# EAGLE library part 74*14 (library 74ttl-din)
Hex schmitt trigger INVERTER
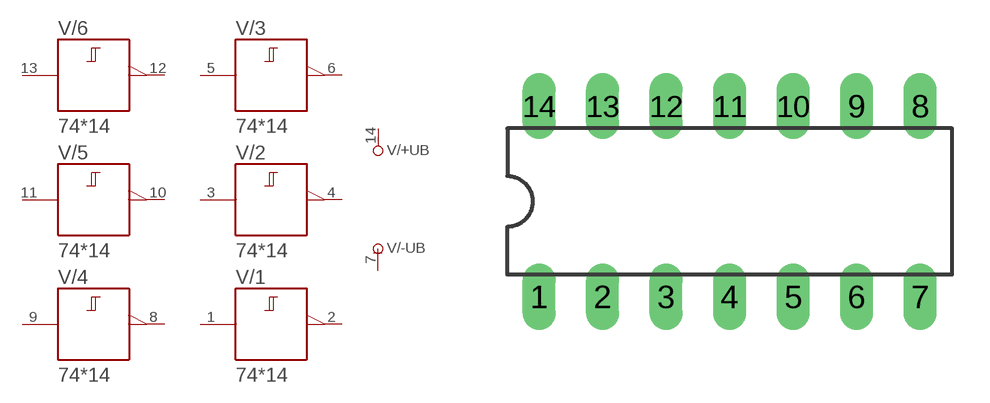
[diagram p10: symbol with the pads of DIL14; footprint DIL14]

Designator prefix V; gates /+UB=+UB /-UB=-UB /1=14 /2=14 /3=14 /4=14 /5=14 /6=14

## 7414N  [DIL14]
1  /1:A  in
2  /1:Y  out
3  /2:A  in
4  /2:Y  out
5  /3:A  in
6  /3:Y  out
7  /-UB:-UB  pwr
8  /4:Y  out
9  /4:A  in
10  /5:Y  out
11  /5:A  in
12  /6:Y  out
13  /6:A  in
14  /+UB:+UB  pwr

## Footprint DIL14 (pad centres in mm)
Dual In Line Package
drill 0.813 long: 1 -7.62,-3.81; 2 -5.08,-3.81; 3 -2.54,-3.81; 4 0,-3.81; 5 2.54,-3.81; 6 5.08,-3.81; 7 7.62,-3.81; 8 7.62,3.81; 9 5.08,3.81; 10 2.54,3.81; 11 0,3.81; 12 -2.54,3.81; 13 -5.08,3.81; 14 -7.62,3.81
